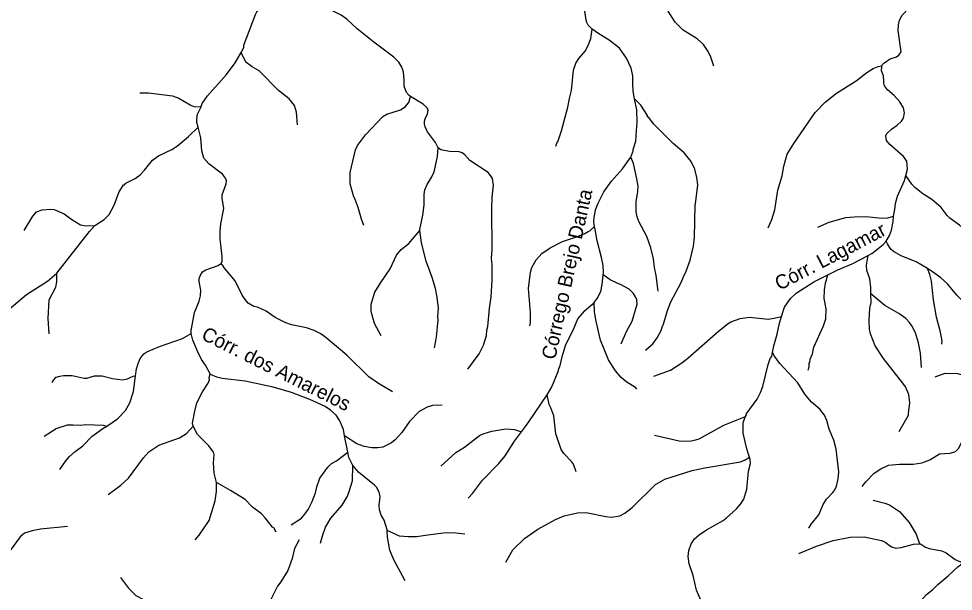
# Model space of a CAD drawing. Extents: x 280.4 to 335.6, y 8893.9 to 8949.5.
# Drawn here: x 293.02 to 303.6, y 8937.49 to 8943.96 of the extents above; entities that cross this region are included whole.
import ezdxf
from ezdxf.enums import TextEntityAlignment as Align

# ---------------------------------------------------------------- set-up
doc = ezdxf.new("R2010")
doc.units = 0
doc.header["$LTSCALE"] = 0.064
doc.linetypes.add('LONG_DASHED', pattern=[7.5, 6, -1.5])
doc.layers.add('61', color=7, linetype='Continuous')
doc.layers.add('7', color=7, linetype='Continuous', lineweight=25)
doc.layers.add('9', color=7, linetype='LONG_DASHED', lineweight=25)

msp = doc.modelspace()

# ---------------------------------------------------------------- linework, layer by layer
at = {"layer": '7'}
msp.add_line((296.7455, 8939.0601), (296.7106, 8939.2441), dxfattribs=at)
for points in [[(299.5114, 8943.843), (299.4826, 8943.8704), (299.4672, 8943.8877), (299.4494, 8943.9189), (299.4426, 8943.9465), (299.4064, 8944.2011), (299.4334, 8944.3444), (299.4307, 8944.4221), (299.4255, 8944.4452), (299.4161, 8944.4634), (299.3701, 8944.5173), (299.3559, 8944.5364), (299.3459, 8944.5619), (299.3447, 8944.6035), (299.3517, 8944.646), (299.3697, 8944.6843), (299.4019, 8944.7532), (299.4127, 8944.7937), (299.4129, 8944.8022)], [(300.8864, 8943.4259), (300.8533, 8943.5268), (300.8236, 8943.5896), (300.7705, 8943.6702), (300.697, 8943.7336), (300.5406, 8943.8303), (300.4482, 8943.9203), (300.3684, 8944.0462), (300.3431, 8944.1068), (300.3245, 8944.1908), (300.3099, 8944.3642), (300.2945, 8944.4245), (300.2656, 8944.4831), (300.209, 8944.5232), (300.1661, 8944.544), (300.0412, 8944.5733), (299.9756, 8944.5969), (299.9031, 8944.6366), (299.7948, 8944.7129), (299.7383, 8944.7257), (299.6519, 8944.7226), (299.569, 8944.7347), (299.4129, 8944.8022)], [(297.4542, 8943.0821), (297.4388, 8943.0915), (297.4099, 8943.1274), (297.3833, 8943.1991), (297.3847, 8943.2712), (297.3748, 8943.3583), (297.3558, 8943.415), (297.3242, 8943.4694), (297.2656, 8943.5279), (297.0394, 8943.6942), (296.8514, 8943.8473), (296.7371, 8943.9548), (296.67, 8943.9996), (296.5072, 8944.0853), (296.45, 8944.124), (296.4103, 8944.1627), (296.3252, 8944.2788), (296.2703, 8944.3899), (296.2431, 8944.5058), (296.2367, 8944.6803)], [(302.7885, 8943.429), (302.7925, 8943.4401), (302.8109, 8943.4599), (302.838, 8943.4776), (302.8825, 8943.5066), (302.9517, 8943.5288), (302.9779, 8943.5476), (303.0042, 8943.5866), (302.9729, 8943.8286), (302.9759, 8943.8934), (302.9854, 8943.943), (303.0186, 8944.001), (303.1679, 8944.1594), (303.2102, 8944.1837), (303.3389, 8944.2108), (303.4174, 8944.2404), (303.503, 8944.3016), (303.5464, 8944.3335)], [(295.54, 8943.5802), (295.5698, 8943.634), (295.572, 8943.6636), (295.7012, 8944.0099), (295.7174, 8944.0387), (295.7589, 8944.0889)], [(299.0987, 8942.5194), (299.1152, 8942.5643), (299.1216, 8942.568), (299.1634, 8942.6921), (299.2336, 8942.9601), (299.2549, 8943.0579), (299.275, 8943.1506), (299.2998, 8943.3804), (299.3271, 8943.46), (299.3596, 8943.5097), (299.4299, 8943.5945), (299.4706, 8943.6661), (299.4958, 8943.7358), (299.5114, 8943.843)], [(299.9913, 8943.056), (299.9759, 8943.141), (299.9693, 8943.2281), (299.9722, 8943.3157), (299.953, 8943.4022), (299.9005, 8943.5166), (299.8207, 8943.6299), (299.7013, 8943.7193), (299.5845, 8943.7897), (299.5114, 8943.843)], [(295.0861, 8942.9629), (295.0882, 8942.9672), (295.098, 8943.0016), (295.1582, 8943.0879), (295.3741, 8943.3286), (295.4741, 8943.4614), (295.54, 8943.5802)], [(296.1762, 8942.7627), (296.1667, 8942.905), (296.145, 8942.9791), (296.084, 8943.0566), (295.962, 8943.1499), (295.7452, 8943.3716), (295.6656, 8943.416), (295.5934, 8943.4715), (295.54, 8943.5802)], [(301.5003, 8941.5956), (301.5427, 8941.69), (301.5761, 8941.8008), (301.6089, 8942.0207), (301.6613, 8942.183), (301.6615, 8942.1836), (301.677, 8942.2934), (301.7174, 8942.4291), (301.79, 8942.551), (302.0339, 8942.9022), (302.146, 8943.0161), (302.2756, 8943.121), (302.4961, 8943.2597), (302.6172, 8943.3515), (302.6909, 8943.3994), (302.7475, 8943.4219), (302.7885, 8943.429)], [(303.0599, 8942.1887), (303.0775, 8942.2582), (303.0686, 8942.3486), (303.0326, 8942.4047), (302.8768, 8942.538), (302.8381, 8942.5845), (302.832, 8942.6356), (302.845, 8942.6642), (302.8964, 8942.7133), (302.9591, 8942.7558), (303.0089, 8942.8027), (303.0305, 8942.8367), (303.0428, 8942.8962), (303.0314, 8942.9544), (302.9926, 8943.0229), (302.9263, 8943.0928), (302.8496, 8943.157), (302.8179, 8943.2014), (302.8096, 8943.2328), (302.8084, 8943.2591), (302.806, 8943.3142), (302.7843, 8943.3721), (302.7858, 8943.4213), (302.7885, 8943.429)], [(294.3939, 8943.1238), (294.4928, 8943.1248), (294.764, 8943.0883), (294.8352, 8943.0619), (294.962, 8942.9875), (295.0046, 8942.97), (295.0861, 8942.9629)], [(296.9268, 8941.6223), (296.8996, 8941.6962), (296.8641, 8941.8246), (296.8299, 8941.9174), (296.8091, 8941.9565), (296.7717, 8942.0935), (296.773, 8942.2223), (296.8337, 8942.4787), (296.8577, 8942.5271), (296.9455, 8942.6488), (297.1429, 8942.854), (297.1877, 8942.883), (297.3408, 8942.9301), (297.397, 8942.9645), (297.4374, 8943.013), (297.4542, 8943.0821)], [(297.7685, 8942.5006), (297.7386, 8942.5629), (297.6466, 8942.6835), (297.6211, 8942.7383), (297.6129, 8942.7716), (297.6141, 8942.803), (297.6203, 8942.8294), (297.6489, 8942.8872), (297.6563, 8942.9255), (297.6453, 8942.9526), (297.5983, 8942.9941), (297.4542, 8943.0821)], [(299.9496, 8942.3972), (299.9688, 8942.4563), (299.9755, 8942.462), (299.9759, 8942.4833), (300.0041, 8942.578), (300.0134, 8942.6963), (300.0204, 8942.7858), (300.014, 8942.9306), (299.9913, 8943.056)], [(300.1146, 8940.2138), (300.1959, 8940.2857), (300.2475, 8940.3534), (300.2926, 8940.434), (300.3069, 8940.4886), (300.3156, 8940.4977), (300.3623, 8940.6623), (300.3997, 8940.7594), (300.5181, 8940.9777), (300.5419, 8941.041), (300.5754, 8941.1051), (300.6199, 8941.2322), (300.658, 8941.39), (300.6697, 8941.4881), (300.6748, 8941.859), (300.681, 8941.8709), (300.6876, 8941.9289), (300.7049, 8942.0813), (300.6951, 8942.1652), (300.6702, 8942.2581), (300.6316, 8942.3453), (300.5514, 8942.4435), (300.4277, 8942.5497), (300.2075, 8942.7682), (300.1482, 8942.8463), (300.1361, 8942.8532), (300.1353, 8942.8657), (300.0619, 8942.9825), (299.9913, 8943.056)], [(295.0525, 8942.7335), (295.038, 8942.7865), (295.0374, 8942.8254), (295.0476, 8942.8828), (295.0861, 8942.9629)], [(293.8845, 8941.6221), (293.9914, 8941.6918), (294.0456, 8941.748), (294.1035, 8941.8541), (294.1567, 8941.9957), (294.2106, 8942.0816), (294.2204, 8942.0828), (294.2375, 8942.1017), (294.3409, 8942.1554), (294.3961, 8942.1962), (294.4465, 8942.2479), (294.5357, 8942.3608), (294.6047, 8942.4095), (294.7579, 8942.4821), (294.8194, 8942.5245), (294.9432, 8942.6279), (295.0525, 8942.7335)], [(295.3169, 8941.1986), (295.3245, 8941.2186), (295.3266, 8941.2739), (295.3043, 8941.4697), (295.3029, 8941.5625), (295.3092, 8941.643), (295.344, 8941.8134), (295.3251, 8941.9302), (295.3251, 8941.9706), (295.3692, 8942.0932), (295.3729, 8942.1317), (295.3641, 8942.1593), (295.3274, 8942.2029), (295.1751, 8942.3184), (295.1191, 8942.384), (295.097, 8942.4664), (295.0852, 8942.614), (295.0525, 8942.7335)], [(297.5626, 8941.5662), (297.5611, 8941.577), (297.5956, 8941.74), (297.6117, 8941.8551), (297.6088, 8941.9718), (297.6177, 8942.0266), (297.6436, 8942.0863), (297.6983, 8942.1734), (297.7236, 8942.2302), (297.762, 8942.4021), (297.7685, 8942.5006)], [(298.1033, 8939.9995), (298.2328, 8940.1723), (298.2804, 8940.2701), (298.3155, 8940.3806), (298.3194, 8940.4378), (298.3315, 8940.4804), (298.3509, 8940.6861), (298.37, 8940.8178), (298.3796, 8941.005), (298.3796, 8941.1785), (298.3733, 8941.2546), (298.3797, 8941.3529), (298.3749, 8941.8093), (298.3797, 8941.943), (298.3955, 8942.0772), (298.3817, 8942.1528), (298.362, 8942.1892), (298.3334, 8942.2223), (298.1286, 8942.3573), (298.0712, 8942.4209), (298.0405, 8942.4435), (298.0044, 8942.4568), (297.896, 8942.4596), (297.7994, 8942.4779), (297.7685, 8942.5006)], [(299.5352, 8941.6104), (299.5309, 8941.6614), (299.5323, 8941.7138), (299.5394, 8941.7494), (299.5479, 8941.8002), (299.5772, 8941.8751), (299.6423, 8942.0051), (299.7296, 8942.1229), (299.8529, 8942.2641), (299.9496, 8942.3972)], [(300.2567, 8940.8806), (300.2361, 8941.0577), (300.2145, 8941.1466), (300.2026, 8941.2457), (300.1755, 8941.3704), (300.1278, 8941.4978), (300.0379, 8941.667), (300.0186, 8941.7215), (300.0076, 8941.7771), (300.0077, 8941.8911), (300.0269, 8942.0085), (300.0296, 8942.0688), (300.0171, 8942.1516), (299.9774, 8942.3229), (299.9496, 8942.3972)], [(302.9194, 8941.7278), (302.9282, 8941.7667), (302.9327, 8941.8049), (302.9423, 8941.873), (302.9648, 8941.9558), (303.0452, 8942.1305), (303.0599, 8942.1887)], [(303.9339, 8941.2531), (303.8336, 8941.3699), (303.7688, 8941.4783), (303.7339, 8941.5496), (303.7009, 8941.5953), (303.6646, 8941.6283), (303.5578, 8941.7049), (303.5256, 8941.7373), (303.4588, 8941.8278), (303.3523, 8941.9154), (303.2497, 8941.9822), (303.1587, 8942.0544), (303.1252, 8942.0915), (303.0599, 8942.1887)], [(293.0865, 8941.5675), (293.1841, 8941.7293), (293.227, 8941.7762), (293.2901, 8941.7988), (293.3796, 8941.8086), (293.4264, 8941.8049), (293.5389, 8941.7534), (293.6231, 8941.6911), (293.7248, 8941.631), (293.7858, 8941.6184), (293.8845, 8941.6221)], [(302.062, 8941.6049), (302.1904, 8941.662), (302.3809, 8941.7126), (302.4762, 8941.7223), (302.6063, 8941.7256), (302.7927, 8941.7043), (302.8538, 8941.7097), (302.9194, 8941.7278)], [(302.836, 8941.4442), (302.8754, 8941.5088), (302.8959, 8941.572), (302.915, 8941.668), (302.9194, 8941.7278)], [(293.457, 8941.0833), (293.8239, 8941.555), (293.8845, 8941.6221)], [(297.1234, 8940.3741), (297.0467, 8940.5142), (297.0107, 8940.6515), (297.0107, 8940.7329), (297.054, 8940.8682), (297.1191, 8940.978), (297.2274, 8941.134), (297.2958, 8941.2878), (297.3502, 8941.3532), (297.4364, 8941.419), (297.5626, 8941.5662)], [(297.727, 8940.239), (297.7489, 8940.3609), (297.7695, 8940.5571), (297.7656, 8940.5917), (297.7718, 8940.6868), (297.7592, 8940.8132), (297.7401, 8940.9091), (297.7024, 8941.035), (297.6342, 8941.2209), (297.5817, 8941.4281), (297.5626, 8941.5662)], [(298.804, 8940.4886), (298.8148, 8940.5239), (298.813, 8940.6373), (298.7909, 8940.91), (298.8115, 8941.0954), (298.8294, 8941.1466), (298.879, 8941.2351), (298.9396, 8941.3058), (299.0347, 8941.3703), (299.1735, 8941.4411), (299.3455, 8941.4968), (299.4293, 8941.5324), (299.4648, 8941.5533), (299.4837, 8941.5644), (299.5352, 8941.6104)], [(299.6369, 8941.0637), (299.6395, 8941.0874), (299.6349, 8941.1708), (299.6178, 8941.2601), (299.5657, 8941.4502), (299.5433, 8941.5781), (299.5352, 8941.6104)], [(302.6323, 8941.283), (302.673, 8941.3078), (302.7462, 8941.3613), (302.8004, 8941.4078), (302.836, 8941.4442)], [(303.3021, 8941.1354), (303.1749, 8941.2133), (303.0142, 8941.2762), (302.9185, 8941.3289), (302.8927, 8941.3521), (302.8735, 8941.3791), (302.8512, 8941.4148), (302.836, 8941.4442)], [(302.1757, 8941.0641), (302.2892, 8941.1205), (302.4529, 8941.1905), (302.6323, 8941.283)], [(302.6637, 8940.8492), (302.6623, 8940.9202), (302.6496, 8941.0186), (302.6193, 8941.1147), (302.6145, 8941.176), (302.6238, 8941.2435), (302.6323, 8941.283)], [(294.9765, 8940.4002), (294.9738, 8940.4449), (294.9798, 8940.454), (295.0117, 8940.638), (295.0659, 8940.766), (295.0818, 8940.8292), (295.0851, 8940.8932), (295.066, 8940.9899), (295.0662, 8941.0225), (295.0756, 8941.0538), (295.1026, 8941.1006), (295.1396, 8941.1209), (295.2808, 8941.1692), (295.3169, 8941.1986)], [(297.2523, 8939.7436), (297.0944, 8939.8348), (296.985, 8939.9107), (296.735, 8940.1555), (296.5003, 8940.3538), (296.4397, 8940.3965), (296.3662, 8940.4342), (296.2789, 8940.465), (296.1082, 8940.4998), (296.0464, 8940.5219), (295.9263, 8940.5837), (295.8224, 8940.6548), (295.7232, 8940.6981), (295.6851, 8940.7087), (295.6195, 8940.744), (295.5838, 8940.7844), (295.5518, 8940.837), (295.4736, 8940.9962), (295.3525, 8941.1416), (295.3347, 8941.1719), (295.3221, 8941.1789), (295.3169, 8941.1986)], [(304.1036, 8940.4106), (304.0494, 8940.4617), (303.9558, 8940.5314), (303.8375, 8940.6512), (303.758, 8940.7146), (303.6369, 8940.8345), (303.5287, 8940.9631), (303.4555, 8941.0298), (303.3602, 8941.0999), (303.3021, 8941.1354)], [(303.4666, 8940.2813), (303.468, 8940.3159), (303.4507, 8940.4173), (303.4067, 8940.5877), (303.3697, 8940.7805), (303.3499, 8940.993), (303.3298, 8941.0685), (303.3021, 8941.1354)], [(292.7541, 8940.1519), (292.7272, 8940.2233), (292.7234, 8940.2875), (292.763, 8940.4174), (292.7873, 8940.5392), (292.8183, 8940.5941), (293.1138, 8940.8416), (293.3502, 8940.9921), (293.457, 8941.0833)], [(293.3679, 8940.3996), (293.3568, 8940.5718), (293.3676, 8940.7805), (293.4428, 8940.9249), (293.454, 8940.9841), (293.457, 8941.0833)], [(299.5324, 8940.7525), (299.5688, 8940.7985), (299.6086, 8940.877), (299.6252, 8940.9562), (299.6369, 8941.0637)], [(299.8369, 8940.2852), (299.8984, 8940.4228), (299.9632, 8940.5395), (300.02, 8940.7318), (300.0143, 8940.7806), (300.0009, 8940.8176), (299.9783, 8940.8545), (299.9298, 8940.9011), (299.83, 8940.957), (299.8004, 8940.9657), (299.7149, 8941.0099), (299.6369, 8941.0637)], [(301.6535, 8940.5956), (301.685, 8940.6987), (301.7541, 8940.7979), (301.817, 8940.856), (302.0195, 8940.9866), (302.1757, 8941.0641)], [(301.9551, 8939.9854), (301.9658, 8940.0254), (301.9656, 8940.0684), (301.9714, 8940.0725), (301.9778, 8940.1107), (302.0023, 8940.1724), (302.0198, 8940.2484), (302.1283, 8940.4877), (302.1541, 8940.569), (302.157, 8940.6821), (302.1364, 8940.798), (302.1379, 8940.8939), (302.1507, 8940.9706), (302.1757, 8941.0641)], [(302.9834, 8939.2951), (303.0878, 8939.4776), (303.0911, 8939.5475), (303.0973, 8939.553), (303.1037, 8939.617), (303.0911, 8939.713), (303.0542, 8939.7968), (303.0254, 8939.8415), (302.8071, 8940.1179), (302.7121, 8940.2606), (302.6571, 8940.398), (302.6468, 8940.4497), (302.6432, 8940.5482), (302.6529, 8940.6884), (302.6656, 8940.7538), (302.6637, 8940.8492)], [(303.2369, 8940.018), (303.2252, 8940.1782), (303.2031, 8940.295), (303.1677, 8940.4109), (303.1283, 8940.4892), (303.1017, 8940.5266), (303.0591, 8940.5704), (302.9785, 8940.6272), (302.8195, 8940.7173), (302.6637, 8940.8492)], [(299.0021, 8939.7091), (299.0543, 8939.7985), (299.1275, 8939.9711), (299.1317, 8940.0047), (299.1441, 8940.0263), (299.1733, 8940.1534), (299.2111, 8940.279), (299.2963, 8940.4404), (299.3488, 8940.5676), (299.4229, 8940.6558), (299.425, 8940.6583), (299.5193, 8940.736), (299.5324, 8940.7525)], [(300.0144, 8939.7707), (300, 8939.7909), (299.8961, 8939.8568), (299.838, 8939.9056), (299.775, 8939.9779), (299.6971, 8940.1047), (299.6057, 8940.3281), (299.5503, 8940.5549), (299.5374, 8940.6516), (299.5324, 8940.7525)], [(300.208, 8939.92), (300.3973, 8939.9886), (300.5237, 8940.0684), (300.5938, 8940.1224), (300.9413, 8940.428), (301.0495, 8940.5162), (301.0807, 8940.5348), (301.1847, 8940.5708), (301.2885, 8940.5866), (301.5013, 8940.5645), (301.571, 8940.5739), (301.6535, 8940.5956)], [(301.551, 8940.1874), (301.5638, 8940.2605), (301.6049, 8940.3931), (301.6298, 8940.518), (301.6535, 8940.5956)], [(294.3467, 8939.9236), (294.3494, 8939.9444), (294.3531, 8939.9771), (294.3565, 8940.0009), (294.3765, 8940.0634), (294.3994, 8940.1173), (294.4379, 8940.1729), (294.4728, 8940.196), (294.6175, 8940.2554), (294.8779, 8940.3456), (294.9765, 8940.4002)], [(295.1881, 8939.945), (295.1363, 8940.043), (295.0928, 8940.1077), (295.0448, 8940.2037), (294.9935, 8940.3281), (294.9765, 8940.4002)], [(301.246, 8939.4626), (301.2557, 8939.4805), (301.2512, 8939.4909), (301.3757, 8939.6609), (301.415, 8939.7328), (301.44, 8939.8016), (301.5016, 8940.0501), (301.5255, 8940.1197), (301.5427, 8940.1402), (301.551, 8940.1874)], [(301.9631, 8938.2009), (301.9896, 8938.2472), (302.0735, 8938.3523), (302.1224, 8938.4684), (302.1603, 8938.5269), (302.2338, 8938.6022), (302.2565, 8938.6349), (302.2737, 8938.6752), (302.2947, 8938.758), (302.2995, 8938.837), (302.2724, 8939.0956), (302.2445, 8939.1938), (302.1925, 8939.3195), (302.1645, 8939.4177), (302.1386, 8939.4785), (302.0862, 8939.5443), (301.9924, 8939.6241), (301.9156, 8939.7169), (301.8367, 8939.8437), (301.6352, 8940.061), (301.5734, 8940.1456), (301.551, 8940.1874)], [(293.4035, 8939.8491), (293.4213, 8939.8794), (293.4489, 8939.9067), (293.4873, 8939.9202), (293.5325, 8939.9262), (293.6298, 8939.9262), (293.7649, 8939.896), (293.7961, 8939.8977), (293.881, 8939.9245), (293.9672, 8939.9248), (294.0841, 8939.8912), (294.1976, 8939.8769), (294.2552, 8939.8907), (294.2832, 8939.9057), (294.3186, 8939.9192), (294.3467, 8939.9236)], [(294.0219, 8939.3533), (294.1431, 8939.4386), (294.2322, 8939.5307), (294.2801, 8939.6161), (294.3236, 8939.7449), (294.3467, 8939.9236)], [(294.9985, 8939.3533), (294.9914, 8939.3861), (295.0149, 8939.5225), (295.0401, 8939.6169), (295.1044, 8939.7429), (295.1675, 8939.84), (295.1809, 8939.8786), (295.1797, 8939.9055), (295.1881, 8939.945)], [(296.7106, 8939.2441), (296.6972, 8939.3147), (296.6556, 8939.4129), (296.6151, 8939.4775), (296.55, 8939.5361), (296.4909, 8939.5745), (296.3173, 8939.6547), (296.1093, 8939.7342), (295.9032, 8939.7938), (295.5858, 8939.8637), (295.3266, 8939.8946), (295.2635, 8939.909), (295.1919, 8939.9378), (295.1881, 8939.945)], [(303.3911, 8939.9115), (303.5018, 8939.9535), (303.6431, 8939.9505), (303.7361, 8939.9243), (303.7917, 8939.8825), (303.8744, 8939.7499), (303.9425, 8939.6697), (304.0057, 8939.6153), (304.1286, 8939.5391)], [(298.7109, 8939.2903), (298.7554, 8939.3507), (298.7924, 8939.4044), (299.0021, 8939.7091)], [(299.3297, 8938.8384), (299.2978, 8938.923), (299.2787, 8938.955), (299.1901, 8939.0458), (299.1607, 8939.091), (299.1011, 8939.2671), (299.077, 8939.4698), (299.0412, 8939.5599), (299.0252, 8939.6001), (299.0021, 8939.7091)], [(297.8147, 8939.5897), (297.7058, 8939.5883), (297.644, 8939.5696), (297.5545, 8939.5201), (297.4447, 8939.4056), (297.3565, 8939.284), (297.2837, 8939.1999), (297.2416, 8939.1667), (297.1434, 8939.1172), (297.0874, 8939.1076), (297.0171, 8939.1076), (296.93, 8939.1238), (296.8482, 8939.1552), (296.7106, 8939.2441)], [(302.5646, 8938.6722), (302.6056, 8938.7239), (302.7003, 8938.8221), (302.775, 8938.8725), (302.8623, 8938.9124), (302.9858, 8938.9251), (303.143, 8938.9253), (303.2381, 8938.9397), (303.3309, 8938.9748), (303.4408, 8939.0399), (303.5596, 8939.0486), (303.6188, 8939.0677), (303.6571, 8939.1059), (303.7408, 8939.2792), (303.764, 8939.3103), (303.9496, 8939.4602), (304.0301, 8939.5051), (304.1286, 8939.5391)], [(300.2174, 8939.2523), (300.4947, 8939.1894), (300.6097, 8939.1859), (300.6665, 8939.1939), (300.721, 8939.2124), (301.0018, 8939.3647), (301.246, 8939.4626)], [(301.289, 8939.0021), (301.2802, 8939.039), (301.2608, 8939.0971), (301.2202, 8939.2737), (301.2199, 8939.3899), (301.239, 8939.4497), (301.246, 8939.4626)], [(293.3136, 8939.2409), (293.4464, 8939.3259), (293.5747, 8939.367), (293.6394, 8939.3698), (293.72, 8939.3636), (293.784, 8939.3731), (293.9802, 8939.3667), (294.0219, 8939.3533)], [(293.4906, 8938.8642), (293.5558, 8938.9614), (293.599, 8939.0125), (293.6624, 8939.0679), (293.7485, 8939.1303), (293.8559, 8939.2405), (293.9763, 8939.329), (294.0219, 8939.3533)], [(294.035, 8938.5802), (294.1804, 8938.6874), (294.2653, 8938.7674), (294.4343, 8938.9955), (294.4945, 8939.0622), (294.608, 8939.1376), (294.8446, 8939.2207), (294.9225, 8939.2727), (294.9985, 8939.3533)], [(295.2625, 8938.7164), (295.2339, 8938.822), (295.229, 8938.9407), (295.2355, 8939.0311), (295.2288, 8939.0594), (295.1758, 8939.1321), (295.0476, 8939.2609), (294.9985, 8939.3533)], [(297.7977, 8938.9014), (297.9687, 8939.0547), (298.065, 8939.1165), (298.2374, 8939.2466), (298.2773, 8939.2658), (298.3753, 8939.2967), (298.5338, 8939.3223), (298.59, 8939.3183), (298.6333, 8939.3152), (298.7109, 8939.2903)], [(298.1093, 8938.5384), (298.1575, 8938.5917), (298.2712, 8938.7432), (298.4554, 8938.9322), (298.5251, 8939.018), (298.6335, 8939.1852), (298.7109, 8939.2903)], [(296.1052, 8938.2367), (296.2216, 8938.3152), (296.261, 8938.3579), (296.297, 8938.4129), (296.3428, 8938.5025), (296.3807, 8938.5996), (296.3966, 8938.6677), (296.4315, 8938.7662), (296.5192, 8938.8911), (296.5629, 8938.93), (296.617, 8938.9614), (296.7455, 8939.0601)], [(296.8046, 8938.9104), (296.757, 8938.9993), (296.7455, 8939.0601)], [(296.4383, 8938.0291), (296.4604, 8938.114), (296.4957, 8938.2129), (296.5557, 8938.3137), (296.6812, 8938.4598), (296.7381, 8938.5545), (296.7597, 8938.6044), (296.7994, 8938.7341), (296.8046, 8938.9104)], [(297.1929, 8938.1755), (297.1927, 8938.1807), (297.1564, 8938.2895), (297.1227, 8938.3479), (297.1034, 8938.4062), (297.1003, 8938.4623), (297.1131, 8938.5572), (297.0999, 8938.6076), (297.0713, 8938.6645), (297.0502, 8938.6873), (296.8676, 8938.8336), (296.81, 8938.9003), (296.8046, 8938.9104)], [(298.5352, 8937.8154), (298.6116, 8937.9544), (298.7437, 8938.0851), (298.8963, 8938.1879), (299.0961, 8938.2983), (299.1927, 8938.3384), (299.3455, 8938.3734), (299.4415, 8938.3766), (299.667, 8938.3321), (299.731, 8938.3256), (299.8221, 8938.3415), (299.8786, 8938.3694), (299.9645, 8938.4359), (300.2268, 8938.6937), (300.3314, 8938.7559), (300.6409, 8938.8516), (300.7842, 8938.8819), (301.1872, 8938.9506), (301.2416, 8938.9713), (301.289, 8939.0021)], [(300.9528, 8937.1606), (300.8623, 8937.2395), (300.7493, 8937.3616), (300.6893, 8937.498), (300.6527, 8937.6639), (300.6078, 8937.7967), (300.5979, 8937.8815), (300.6043, 8937.9472), (300.6305, 8938.0229), (300.6693, 8938.0802), (300.7227, 8938.1265), (300.8047, 8938.1819), (300.9916, 8938.2882), (301.0316, 8938.3166), (301.1436, 8938.4172), (301.1899, 8938.4701), (301.2253, 8938.5285), (301.2615, 8938.6421), (301.2807, 8938.8436), (301.2997, 8938.93), (301.2994, 8938.9761), (301.289, 8939.0021)], [(295.0198, 8938.0669), (295.066, 8938.1226), (295.1766, 8938.2867), (295.2447, 8938.5093), (295.2625, 8938.6158), (295.2625, 8938.7164)], [(295.937, 8938.1563), (295.9088, 8938.2027), (295.8944, 8938.2122), (295.8128, 8938.319), (295.7701, 8938.3616), (295.67, 8938.4395), (295.5857, 8938.5253), (295.421, 8938.6277), (295.2625, 8938.7164)], [(302.6886, 8938.5162), (302.821, 8938.4841), (302.8743, 8938.4633), (302.9887, 8938.3878), (303.0968, 8938.2654), (303.1745, 8938.1328), (303.2127, 8938.023)], [(298.0695, 8938.1315), (297.9699, 8938.1447), (297.8582, 8938.1479), (297.653, 8938.1203), (297.5249, 8938.1031), (297.4289, 8938.1016), (297.333, 8938.1098), (297.1929, 8938.1755)], [(297.396, 8937.6063), (297.2684, 8937.8437), (297.2235, 8937.9505), (297.1964, 8938.1), (297.1929, 8938.1755)], [(296.1968, 8938.0679), (296.1433, 8937.969), (296.1182, 8937.8586), (296.0684, 8937.7235), (295.9891, 8937.5937), (295.951, 8937.5447), (295.854, 8937.3494), (295.7886, 8937.2615), (295.6369, 8937.1068), (295.508, 8936.9585), (295.4293, 8936.8426)], [(301.8483, 8937.9123), (302.0465, 8937.9981), (302.2371, 8938.0616), (302.4296, 8938.0968), (302.5856, 8938.1015), (302.7846, 8938.0613), (302.8255, 8938.0408), (302.896, 8937.9897), (302.9439, 8937.9754), (303.0056, 8937.9804), (303.144, 8938.0197), (303.2127, 8938.023)], [(303.2127, 8938.023), (303.2238, 8938.0235), (303.282, 8937.9862), (303.3218, 8937.9713), (303.4666, 8937.9457), (303.5164, 8937.9207), (303.6166, 8937.8461), (303.6757, 8937.8189), (303.7125, 8937.8119)], [(303.1512, 8937.2395), (303.1605, 8937.2815), (303.2274, 8937.3805), (303.2926, 8937.449), (303.3651, 8937.5087), (303.4195, 8937.5647), (303.5375, 8937.6606), (303.6463, 8937.7623), (303.7125, 8937.8119)], [(294.1738, 8937.6444), (294.2669, 8937.5222), (294.3492, 8937.4378), (294.4365, 8937.3929), (294.628, 8937.3455), (294.6581, 8937.3291), (294.8686, 8937.1715), (294.9296, 8937.1042), (294.9842, 8937.0257), (295.0303, 8936.9842), (295.1133, 8936.9535), (295.3506, 8936.9069), (295.4016, 8936.8843), (295.4293, 8936.8426)]]:
    msp.add_lwpolyline(points, dxfattribs=at)
at = {"layer": '9'}
msp.add_lwpolyline([(293.5753, 8938.2188), (293.2698, 8938.1897), (293.1763, 8938.1716), (293.0907, 8938.1445), (293.04, 8938.1024), (292.7751, 8937.7411), (292.7273, 8937.7009), (292.6527, 8937.6692), (292.5064, 8937.6213), (292.4104, 8937.608), (292.3048, 8937.6118), (292.2311, 8937.6276)], dxfattribs=at)

# ---------------------------------------------------------------- texts
at = {"layer": '61'}
for s, rotation, p in [('Córrego Brejo Danta', 77.569, (299.3032, 8941.0557)), ('Córr. Lagamar', 27.646, (302.2405, 8941.2035)), ('Córr. dos Amarelos', 333.454, (295.9029, 8939.9311))]:
    msp.add_text(s, height=0.16, rotation=rotation, dxfattribs=at).set_placement(p, align=Align.CENTER)

doc.saveas('drawing.dxf')
